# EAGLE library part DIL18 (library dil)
SOCKET Dual In Line
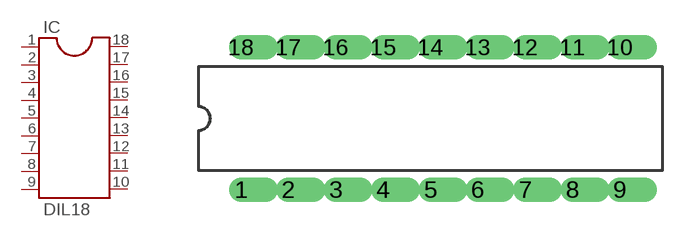
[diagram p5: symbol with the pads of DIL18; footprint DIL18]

Designator prefix IC

## DIL18  [DIL18]
1  1  pas
2  2  pas
3  3  pas
4  4  pas
5  5  pas
6  6  pas
7  7  pas
8  8  pas
9  9  pas
10  10  pas
11  11  pas
12  12  pas
13  13  pas
14  14  pas
15  15  pas
16  16  pas
17  17  pas
18  18  pas

## Footprint DIL18 (pad centres in mm)
SOCKET Dual In Line
drill 0.813 offset: 1 -10.16,-3.81; 2 -7.62,-3.81; 3 -5.08,-3.81; 4 -2.54,-3.81; 5 0,-3.81; 6 2.54,-3.81; 7 5.08,-3.81; 8 7.62,-3.81; 9 10.16,-3.81; 10 10.16,3.81; 11 7.62,3.81; 12 5.08,3.81; 13 2.54,3.81; 14 0,3.81; 15 -2.54,3.81; 16 -5.08,3.81; 17 -7.62,3.81; 18 -10.16,3.81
